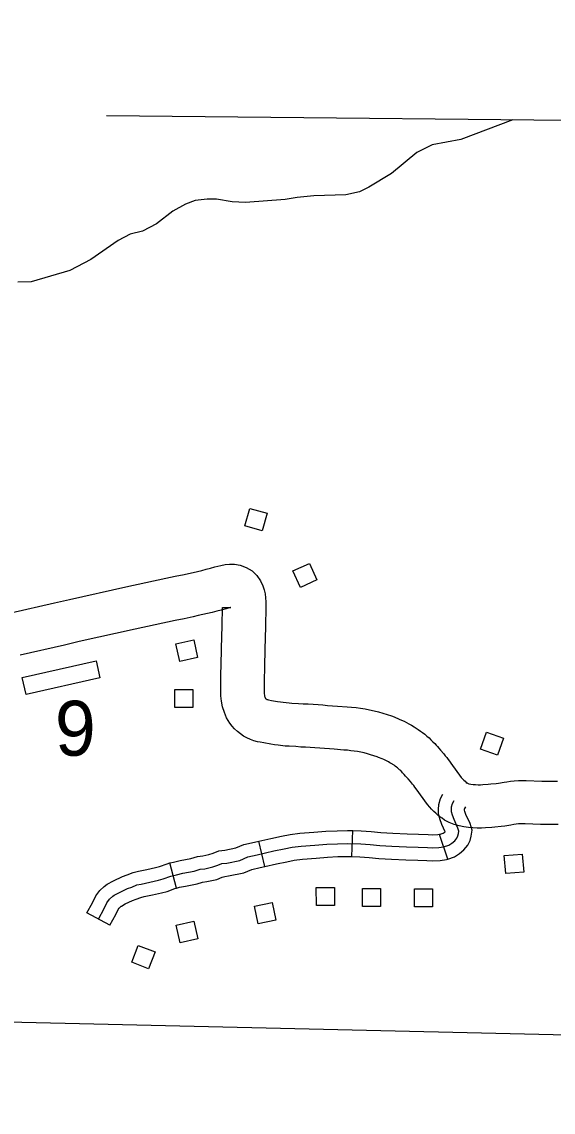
# Model space of a CAD drawing. Extents: x -19 to 366, y -4 to 359.
# Drawn here: x 137.637 to 138.218, y 202.996 to 204.187 of the extents above; entities that cross this region are included whole.
import ezdxf

# ---------------------------------------------------------------- set-up
doc = ezdxf.new("R2010")
doc.units = 0
for name, color, linetype in [('21', 7, 'Continuous'), ('R_Alt Surface', 7, 'Continuous'), ('R_Axis Annot', 7, 'Continuous'), ('R_Contour Annot', 7, 'Continuous'), ('R_ROW Annot', 7, 'Continuous'), ('R_Temp Easement', 7, 'Continuous'), ('Sheet Fence', 7, 'Continuous')]:
    doc.layers.add(name, color=color, linetype=linetype)

msp = doc.modelspace()

# ---------------------------------------------------------------- linework, layer by layer
at = {"layer": '21'}
for points in [[(137.8993, 203.6308), (137.8804, 203.6362), (137.8858, 203.6552), (137.9048, 203.6498)], [(137.9413, 203.5689), (137.9331, 203.5868), (137.951, 203.5951), (137.9593, 203.5772)], [(137.8095, 203.4881), (137.8052, 203.5073), (137.8246, 203.5116), (137.8288, 203.4923)], [(137.6413, 203.452), (137.6371, 203.4704), (137.7179, 203.4887), (137.7221, 203.4702)], [(137.8041, 203.4375), (137.804, 203.4572), (137.8238, 203.4572), (137.8238, 203.4375)], [(138.1632, 203.4041), (138.1565, 203.3856), (138.1379, 203.3922), (138.1445, 203.4108)], [(138.1658, 203.2562), (138.1641, 203.2758), (138.1837, 203.2776), (138.1855, 203.2579)], [(137.9587, 203.2214), (137.9586, 203.2411), (137.9784, 203.2411), (137.9784, 203.2214)], [(138.0091, 203.2203), (138.0091, 203.24), (138.0289, 203.24), (138.0289, 203.2203)], [(138.066, 203.2198), (138.0659, 203.2395), (138.0857, 203.2395), (138.0857, 203.2198)], [(137.8951, 203.2013), (137.891, 203.2205), (137.9103, 203.2247), (137.9145, 203.2054)], [(137.829, 203.1848), (137.8097, 203.1804), (137.8054, 203.1997), (137.8246, 203.2041)], [(137.7568, 203.1593), (137.7639, 203.1777), (137.7823, 203.1706), (137.7752, 203.1522)]]:
    msp.add_lwpolyline(points, close=True, dxfattribs=at)
at = {"layer": 'R_Alt Surface'}
msp.add_lwpolyline([(139.3896, 204.0685), (138.383, 204.0778), (138.3761, 204.0776), (137.7294, 204.084)], dxfattribs=at)
at = {"layer": 'R_Axis Annot'}
msp.add_lwpolyline([(137.3855, 203.0998), (138.3744, 203.0767)], dxfattribs=at)
at = {"layer": 'R_Contour Annot'}
for p, q in [((137.6726, 203.552), (137.6889, 203.5558)), ((137.6247, 203.5411), (137.6726, 203.552)), ((137.865, 203.5468), (137.8653, 203.5468)), ((137.6832, 203.5059), (137.6349, 203.4949)), ((137.6994, 203.5096), (137.6832, 203.5059)), ((137.6832, 203.5059), (137.6832, 203.5059)), ((137.6993, 203.5096), (137.6994, 203.5096)), ((138.1236, 203.355), (138.1228, 203.3556)), ((138.096, 203.3166), (138.0952, 203.3172))]:
    msp.add_line(p, q, dxfattribs=at)
for points in [[(137.6889, 203.5558), (137.7504, 203.5695), (137.7943, 203.5789), (137.8043, 203.5811), (137.8142, 203.5831), (137.819, 203.5842), (137.8239, 203.5853), (137.8333, 203.5875), (137.8382, 203.5887), (137.8431, 203.5899), (137.8478, 203.5912), (137.8543, 203.5929), (137.8589, 203.5938), (137.8638, 203.5942), (137.8659, 203.5942)], [(137.8659, 203.5942), (137.8691, 203.5941), (137.8753, 203.5931), (137.882, 203.5908), (137.8885, 203.5868), (137.8937, 203.5817), (137.8977, 203.5761), (137.9001, 203.5706), (137.9016, 203.5662), (137.9026, 203.5618), (137.9032, 203.5573), (137.9035, 203.5532), (137.9035, 203.5473), (137.9032, 203.5261), (137.9024, 203.5011), (137.902, 203.4823), (137.9019, 203.4789), (137.9018, 203.476), (137.9017, 203.473), (137.9016, 203.47), (137.9016, 203.4642), (137.9016, 203.461), (137.9016, 203.4581), (137.9017, 203.4552), (137.9017, 203.4526), (137.9018, 203.451), (137.902, 203.4502), (137.9023, 203.4492), (137.9027, 203.4482), (137.9032, 203.4475), (137.9035, 203.4471), (137.9035, 203.4471), (137.9037, 203.447), (137.9042, 203.4467), (137.9043, 203.4466), (137.9047, 203.4465), (137.9051, 203.4463), (137.9065, 203.4461), (137.9097, 203.4454), (137.9162, 203.4444), (137.9193, 203.4439), (137.9225, 203.4435), (137.929, 203.4428), (137.932, 203.4425), (137.9391, 203.4421), (137.9444, 203.4418), (137.9496, 203.4415), (137.9605, 203.4408), (137.9658, 203.4404), (137.971, 203.44), (137.9764, 203.4396), (137.9816, 203.4393), (137.9923, 203.4385), (137.997, 203.4381), (138.0021, 203.4375), (138.0069, 203.4369), (138.0119, 203.4361), (138.0168, 203.4351), (138.0217, 203.434), (138.0265, 203.4328), (138.0314, 203.4315), (138.0362, 203.4299), (138.0407, 203.4284), (138.0436, 203.4274), (138.0491, 203.4251), (138.0517, 203.424), (138.0546, 203.4227), (138.0598, 203.42), (138.0626, 203.4185), (138.0654, 203.4167), (138.0701, 203.4137), (138.0726, 203.4119), (138.0748, 203.4103), (138.0772, 203.4085), (138.0795, 203.4065), (138.0818, 203.4045), (138.0839, 203.4025), (138.0861, 203.4003), (138.088, 203.3982), (138.0895, 203.3965), (138.0909, 203.395), (138.0926, 203.3931), (138.0944, 203.3912), (138.0978, 203.3872), (138.0996, 203.385), (138.1013, 203.3829), (138.1028, 203.3809), (138.1043, 203.3789), (138.1058, 203.3769), (138.1171, 203.3612), (138.1178, 203.3604), (138.119, 203.3591), (138.1198, 203.3583), (138.1212, 203.3571), (138.1224, 203.3559), (138.1236, 203.355)], [(137.8653, 203.5468), (137.8651, 203.5468), (137.8649, 203.5468), (137.86, 203.5454), (137.8547, 203.544), (137.8498, 203.5428), (137.8447, 203.5415), (137.8344, 203.5391), (137.8293, 203.538), (137.8241, 203.5368), (137.8141, 203.5347), (137.8043, 203.5326), (137.7606, 203.5232), (137.6993, 203.5096)], [(138.0952, 203.3172), (138.0919, 203.3196), (138.0891, 203.3223), (138.0869, 203.3242), (138.0845, 203.3267), (138.0825, 203.3289), (138.0801, 203.3317), (138.0676, 203.3489), (138.0664, 203.3506), (138.0651, 203.3523), (138.0639, 203.3539), (138.0626, 203.3555), (138.0616, 203.3568), (138.059, 203.3597), (138.0576, 203.3613), (138.0562, 203.3628), (138.0545, 203.3646), (138.0529, 203.3664), (138.0519, 203.3675), (138.0508, 203.3687), (138.0497, 203.3697), (138.0485, 203.3707), (138.0475, 203.3716), (138.0462, 203.3725), (138.0448, 203.3736), (138.0436, 203.3745), (138.0404, 203.3765), (138.0391, 203.3773), (138.0375, 203.3782), (138.034, 203.38), (138.0323, 203.3808), (138.0304, 203.3816), (138.0267, 203.3831), (138.0251, 203.3837), (138.0214, 203.385), (138.0179, 203.3861), (138.0144, 203.387), (138.0108, 203.388), (138.0072, 203.3888), (138.0036, 203.3895), (138, 203.39), (137.9963, 203.3905), (137.9926, 203.391), (137.9887, 203.3912), (137.9782, 203.3921), (137.973, 203.3924), (137.9677, 203.3928), (137.9624, 203.3932), (137.9571, 203.3936), (137.9468, 203.3942), (137.9416, 203.3945), (137.9362, 203.3949), (137.9289, 203.3953), (137.9246, 203.3956), (137.9169, 203.3965), (137.9128, 203.397), (137.9088, 203.3976), (137.9011, 203.3989), (137.8971, 203.3997), (137.8942, 203.4002), (137.8904, 203.4013), (137.8866, 203.4027), (137.8828, 203.4044), (137.8789, 203.4065), (137.8757, 203.4088), (137.8724, 203.4113), (137.8693, 203.4144), (137.8667, 203.4172), (137.864, 203.4207), (137.8606, 203.4264), (137.8581, 203.4322), (137.856, 203.4383), (137.8548, 203.4447), (137.8544, 203.4505), (137.8543, 203.4543), (137.8542, 203.4576), (137.8543, 203.461), (137.8542, 203.4642), (137.8543, 203.4709), (137.8544, 203.4741), (137.8544, 203.4774), (137.8546, 203.4807), (137.8547, 203.4835), (137.8551, 203.5023), (137.8558, 203.5272), (137.8561, 203.547), (137.865, 203.5468)], [(138.1228, 203.3556), (138.1234, 203.3552), (138.124, 203.3549), (138.1246, 203.3546), (138.1254, 203.3544), (138.1276, 203.354), (138.1301, 203.3536), (138.1327, 203.3534), (138.1355, 203.3533), (138.1382, 203.3533), (138.1406, 203.3534), (138.1465, 203.3538), (138.1492, 203.3541), (138.1552, 203.3547), (138.1579, 203.3551), (138.1638, 203.356), (138.167, 203.3565), (138.1709, 203.3571), (138.175, 203.3576), (138.1795, 203.3579), (138.1837, 203.358), (138.1879, 203.358), (138.205, 203.3572), (138.207, 203.3572), (138.2222, 203.3573)], [(138.223, 203.3099), (138.2067, 203.3098), (138.2035, 203.3099), (138.1867, 203.3106), (138.1842, 203.3107), (138.1818, 203.3106), (138.1796, 203.3104), (138.1772, 203.3101), (138.1744, 203.3097), (138.1713, 203.3092), (138.1645, 203.3082), (138.1608, 203.3077), (138.1539, 203.307), (138.1503, 203.3066), (138.1434, 203.3062), (138.1393, 203.306), (138.1345, 203.306), (138.1298, 203.3061), (138.1248, 203.3066), (138.1198, 203.3073), (138.1147, 203.3083), (138.1092, 203.3097), (138.1038, 203.312), (138.0988, 203.3146), (138.096, 203.3166)]]:
    msp.add_lwpolyline(points, dxfattribs=at)
at = {"layer": 'R_ROW Annot'}
for p, q in [((137.9976, 203.2748), (137.9985, 203.3032)), ((137.9022, 203.264), (137.8957, 203.2916)), ((138.1024, 203.2721), (138.0932, 203.2989)), ((137.8058, 203.2403), (137.7986, 203.2678)), ((137.733, 203.1998), (137.7079, 203.2132))]:
    msp.add_line(p, q, dxfattribs=at)
for points in [[(138.0932, 203.2989), (138.0971, 203.3003), (138.0984, 203.3011), (138.0995, 203.302), (138.0959, 203.3098), (138.0937, 203.3159), (138.0923, 203.3217), (138.0921, 203.3263), (138.0924, 203.3317), (138.0944, 203.3383), (138.0969, 203.3429)], [(137.7204, 203.2065), (137.7266, 203.218), (137.7297, 203.2244), (137.7326, 203.2282), (137.7361, 203.2315), (137.7377, 203.2328), (137.7434, 203.2357), (137.7523, 203.24), (137.7568, 203.2415), (137.7626, 203.2438), (137.7672, 203.2448), (137.7765, 203.2469), (137.7862, 203.2491), (137.7913, 203.2504), (137.7997, 203.2534), (137.8058, 203.255), (137.8128, 203.2565), (137.825, 203.259), (137.8315, 203.261), (137.8366, 203.2615), (137.8411, 203.2624), (137.8455, 203.2635), (137.8508, 203.2654), (137.8552, 203.2672), (137.8607, 203.2677), (137.8751, 203.2706), (137.8837, 203.2744), (137.8941, 203.2767), (137.912, 203.2809), (137.9234, 203.2832), (137.9322, 203.2849), (137.9421, 203.2861), (137.9571, 203.2873), (137.9701, 203.2884), (137.9818, 203.2889), (137.9928, 203.2891), (138.0071, 203.2887), (138.0173, 203.2879), (138.028, 203.287), (138.0413, 203.2863), (138.0573, 203.2855), (138.0698, 203.285), (138.0802, 203.2848), (138.0854, 203.2844), (138.0926, 203.2848), (138.0977, 203.2854), (138.1033, 203.2874), (138.1067, 203.2895), (138.1099, 203.2921), (138.1121, 203.2949), (138.1132, 203.2974), (138.114, 203.3), (138.1143, 203.3027), (138.1134, 203.3058), (138.1091, 203.3153), (138.1073, 203.32), (138.1064, 203.3237), (138.1063, 203.3261), (138.1065, 203.3293), (138.1076, 203.3328), (138.1094, 203.3361)], [(138.1024, 203.2721), (138.1095, 203.2745), (138.1151, 203.278), (138.12, 203.2821), (138.1242, 203.2873), (138.1266, 203.2925), (138.1279, 203.2971), (138.1288, 203.3038), (138.1268, 203.3108), (138.1222, 203.3207), (138.1209, 203.3242), (138.1206, 203.3256), (138.1206, 203.326), (138.1206, 203.3268), (138.1208, 203.3273), (138.1219, 203.3293)], [(137.8957, 203.2916), (137.9089, 203.2947), (137.9206, 203.2971), (137.93, 203.299), (137.9407, 203.3002), (137.956, 203.3014), (137.9691, 203.3026), (137.9813, 203.3031), (137.9928, 203.3034), (137.9985, 203.3032)], [(137.9985, 203.3032), (138.0078, 203.3029), (138.0185, 203.3021), (138.029, 203.3012), (138.0421, 203.3005), (138.0579, 203.2997), (138.0702, 203.2992), (138.081, 203.299), (138.0857, 203.2986), (138.0913, 203.2989), (138.0944, 203.2993), (138.0932, 203.2989)], [(137.7986, 203.2678), (137.8025, 203.2688), (137.8099, 203.2704), (137.8215, 203.2728), (137.8288, 203.2749), (137.8344, 203.2755), (137.8379, 203.2762), (137.8413, 203.2771), (137.8457, 203.2787), (137.8519, 203.2811), (137.8586, 203.2818), (137.8708, 203.2843), (137.8792, 203.288), (137.8909, 203.2905), (137.8957, 203.2916)], [(137.7079, 203.2132), (137.7139, 203.2244), (137.7175, 203.2319), (137.722, 203.2378), (137.7268, 203.2422), (137.73, 203.2448), (137.7371, 203.2484), (137.7469, 203.2531), (137.7519, 203.2549), (137.7584, 203.2574), (137.7641, 203.2587), (137.7734, 203.2608), (137.7829, 203.2629), (137.7871, 203.264), (137.7955, 203.267), (137.7986, 203.2678)], [(137.9022, 203.264), (137.915, 203.267), (137.9262, 203.2692), (137.9344, 203.2709), (137.9435, 203.272), (137.9583, 203.2731), (137.971, 203.2742), (137.9823, 203.2747), (137.9927, 203.2749), (137.9976, 203.2748)], [(137.9976, 203.2748), (138.0063, 203.2745), (138.0162, 203.2738), (138.0271, 203.2728), (138.0406, 203.2721), (138.0566, 203.2713), (138.0694, 203.2708), (138.0794, 203.2706), (138.0852, 203.2701), (138.094, 203.2706), (138.101, 203.2716), (138.1025, 203.2721)], [(137.8058, 203.2403), (137.809, 203.2412), (137.8157, 203.2426), (137.8285, 203.2452), (137.8343, 203.247), (137.8388, 203.2474), (137.8443, 203.2485), (137.8497, 203.2499), (137.8558, 203.2522), (137.8586, 203.2532), (137.8628, 203.2536), (137.8795, 203.257), (137.8881, 203.2608), (137.8972, 203.2628), (137.9022, 203.264)], [(137.733, 203.1998), (137.7393, 203.2115), (137.7419, 203.2169), (137.7432, 203.2186), (137.7453, 203.2207), (137.7455, 203.2208), (137.7498, 203.223), (137.7577, 203.2268), (137.7617, 203.2282), (137.7668, 203.2301), (137.7704, 203.231), (137.7795, 203.233), (137.7895, 203.2353), (137.7955, 203.2368), (137.8039, 203.2398), (137.8058, 203.2403)]]:
    msp.add_lwpolyline(points, dxfattribs=at)
at = {"layer": 'R_Temp Easement'}
msp.add_lwpolyline([(138.1735, 204.0796), (138.1166, 204.0584), (138.0852, 204.0523), (138.0686, 204.0439), (138.0406, 204.0212), (138.0161, 204.006), (138.0059, 204.0011), (137.9907, 203.9976), (137.956, 203.9965), (137.9378, 203.995), (137.9246, 203.9927), (137.8811, 203.9893), (137.8668, 203.99), (137.8494, 203.993), (137.8392, 203.993), (137.8263, 203.9915), (137.8157, 203.9877), (137.8018, 203.9801), (137.784, 203.9661), (137.7685, 203.9581), (137.7553, 203.9547), (137.7421, 203.9479), (137.7122, 203.927), (137.6892, 203.9152), (137.6468, 203.9027), (137.6325, 203.9023)], dxfattribs=at)
at = {"layer": 'Sheet Fence'}
for points in [[(139.4406, 1.5315), (139.2511, 10.1473), (139.0608, 18.7633), (138.8699, 27.3793), (138.6784, 35.9956), (138.4861, 44.6119), (138.2932, 53.2285), (138.0997, 61.8451), (137.9055, 70.4619), (137.7106, 79.0789), (137.5151, 87.6959), (137.319, 96.3132), (137.1221, 104.9306), (136.9247, 113.5481), (136.7265, 122.1658), (136.5278, 130.7836), (136.3283, 139.4016), (136.1282, 148.0197), (135.9275, 156.6379), (135.7261, 165.2564), (135.5241, 173.8749), (135.3214, 182.4936), (135.1181, 191.1125), (134.9141, 199.7315), (134.7095, 208.3506), (134.5043, 216.9699), (134.2984, 225.5894), (134.0919, 234.209), (133.8847, 242.8288), (133.6769, 251.4487), (133.4685, 260.0687), (133.2594, 268.6889), (133.0497, 277.3093), (132.8393, 285.9298), (132.6283, 294.5504), (132.4167, 303.1713), (132.2044, 311.7922), (131.9916, 320.4133), (131.778, 329.0346), (131.5639, 337.656), (131.3491, 346.2776)], [(0, 198.1326), (7.1014, 198.137), (14.2028, 198.1503), (21.3042, 198.1724), (28.4055, 198.2034), (35.5068, 198.2433), (42.6081, 198.292), (49.7092, 198.3496), (56.8103, 198.4161), (63.9113, 198.4913), (71.0123, 198.5755), (78.1131, 198.6685), (85.2137, 198.7704), (92.3143, 198.8811), (99.4147, 199.0007), (106.5149, 199.1291), (113.615, 199.2664), (120.7149, 199.4126), (127.8146, 199.5676), (134.9141, 199.7315), (142.0135, 199.9042), (149.1125, 200.0858), (156.2114, 200.2762), (163.31, 200.4755), (170.4084, 200.6837), (177.5065, 200.9007), (184.6043, 201.1265), (191.7018, 201.3612), (198.799, 201.6048), (205.896, 201.8572), (212.9926, 202.1185), (220.0888, 202.3886), (227.1848, 202.6676), (234.2803, 202.9554), (241.3755, 203.2521), (248.4704, 203.5576), (255.5648, 203.872), (262.6589, 204.1952), (269.7525, 204.5273), (276.8457, 204.8682), (283.9385, 205.218), (291.0309, 205.5766), (298.1228, 205.9441), (305.2142, 206.3204), (312.3051, 206.7056), (319.3956, 207.0996), (326.4856, 207.5024), (333.5751, 207.9141), (340.664, 208.3347)]]:
    msp.add_spline(points, degree=3, dxfattribs=at)

# ---------------------------------------------------------------- texts
at = {"layer": '21'}
msp.add_text('9', height=0.06, dxfattribs=at).set_placement((137.6729, 203.385))

doc.saveas('drawing.dxf')
